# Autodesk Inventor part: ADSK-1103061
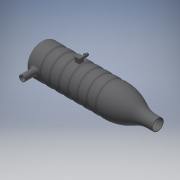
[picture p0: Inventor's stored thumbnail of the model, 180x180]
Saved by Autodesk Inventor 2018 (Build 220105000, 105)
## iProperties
Shininess: 50.0
Length Units: 11272
Angle Units: 11279
Time Units: 11290
Mass Units: 11286
Length Display Precision: 4
Angle Display Precision: 2
Compacted: True
Created: 2000-08
Part Number: ADSK-1103061
Document SubType Name: Modeling
Description: EXHAUST PIPE - SIDE
Mass: 7.18318 g
Surface Area: 233.725 cm^2
Volume: 7.18318 cm^3
Density: 1 g/cm^3
Material: Generic
Appearance: Black
Density: 0.0
Volumn: 0.0
Area: 0.0
PropertySet Name: Model Information
Control State: 0
Master: False
Checked Out: False
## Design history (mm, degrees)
node "Revolution1" dims "d8" = 90 deg
  sketch "Sketch3"
    geometry: L1 (33.387, 39.395)-(33.387, -87.605); L2 (49.262, -64.093)-(49.262, -4.86); L3 (39.387, 32.722)-(39.387, 39.395); L4 (39.387, 39.395)-(33.387, 39.395); L5 (33.387, -87.605)-(36.562, -87.605); L6 (36.562, -87.605)-(49.262, -79.35); L7 (49.262, -79.35)-(49.262, -64.093); L8 (42.607, 20.345)-(43.458, 18.72); A1 r 25.4 centre (64.787, 32.722) between (39.387, 32.722) and (42.607, 20.345); A2 r 50.8 centre (-1.538, -4.86) between (49.262, -4.86) and (43.458, 18.72); 1 further point
    constraints: 16 end point, 4 point on circle, 3 parallel, 3 tangent, 2 centre point, 2 perpendicular, 2 point on line, 1 vertical, 1 other
    dimensions: "d1" = 6.35 diameter of L5.end L1; "d2" = 31.75 diameter of L2.start L1; "d5" = 8.255 vertical distance of L5.end L6.end; "d6" = 127 distance of L1.start L1.end; "d7" = 12 diameter of L3 L1; "d48" = 25.4 radius of A1; "d49" = 6.67308 distance from line of L4 A1.centre; "d50" = 19.05 distance from line of L4 L8.start; "d51" = 31.75 distance from line of point (49.262, 7.645) L4; "d53" = 50.8 radius of A2
node "Fillet1" dims "d9" = 3.175
workaxis "Work Axis1"
node "Revolution2" dims "d15" = 90 deg
  sketch "Sketch4"
    geometry: L1 (49.262, -4.86)-(49.262, -77.627) reference; L2 (33.387, 64.795)-(33.387, -113.005) reference; L3 (49.262, -6.96)-(48.373, -7.595); L4 (48.373, -7.595)-(48.373, -8.865); L5 (48.373, -8.865)-(49.262, -9.5); L6 (27.387, 39.395)-(39.387, 39.395) reference
    constraints: 6 end point, 2 point on line, 1 equal length, 1 parallel
    dimensions: "d11" = 1.27 distance of L3.end L4.end; "d12" = 2.54 distance of L5.end L3.start; "d13" = 46.355 distance from line of L6 L3.start; "d14" = 14.986 distance between parallel lines of L2 L4
node "Fillet2" dims "d16" = 3.175
node "Rectangular Pattern1" dims "d17" = 70, "d19" = 9.525
workplane "Work Plane1"
workplane "Work Plane2"
node "Extrusion1" dims "d23" = 25.4, "d24" = 0
  sketch "Sketch5"
    geometry: L1 (136.516, 0)-(-41.284, 0) reference; L2 (111.116, 6)-(111.116, -6) reference; C1 r 3.175 at (-0.009, 0)
    constraints: 1 centre point, 1 point on line
    dimensions: "d22" = 6.35 diameter of C1; "d54" = 111.125 distance from line of L2 C1.centre
node "Shell1" dims "d25" = 0.6096
node "Fillet5" dims "d81" = 2.54
workaxis "Work Axis2"
workplane "Work Plane3"
workplane "Work Plane4"
node "Extrusion2" dims "d82" = 0, "d83" = 4.7625 (= d85)
  sketch "Sketch6"
    geometry: L1 (-6.25, 20.108)-(-1.487, 20.108); L2 (-1.487, 20.108)-(-1.487, 24.871); L3 (-1.487, 24.871)-(-6.25, 24.871); L4 (-6.25, 24.871)-(-6.25, 20.108); L5 (-3.869, 128.672)-(-3.869, -49.128) reference
    constraints: 8 end point, 2 parallel, 1 horizontal, 1 perpendicular
    dimensions: "d85" = 4.7625 distance of L1.end L2.end; "d84" = 4.7625 distance of L2.end L3.end (= d85); "d98" = 2.38125 distance between parallel lines of L2 L5 (= 0.5 x d84)
node "Extrusion3" dims "d86" = 0, "d87" = 3.175
  sketch "Sketch7"
    geometry: L1 (4.763, 0)-(4.763, 4.762) reference; L2 (0, 4.762)-(4.763, 4.762) reference; C1 r 1.27 at (2.381, 2.381)
    constraints: 1 centre point
    dimensions: "d88" = 2.54 diameter of C1; "d90" = 2.38125 distance from line of C1.centre L2 (= 0.5 x d85); "d89" = 2.38125 distance from line of L1 C1.centre (= d90)
node "Extrusion4" dims "d91" = -12 deg, "d92" = 3.175
  sketch "Sketch8"
    geometry: C1 r 1.27 at (0, 0) reference; C2 r 1.905 at (0, 0)
    constraints: 1 centre point, 1 coincident
    dimensions: "d93" = 3.81 diameter of C2
node "Extrusion6" dims "d104" = 25.4, "d105" = 0
  sketch "Sketch12"
    geometry: L1 (-6.25, 20.108)-(-6.25, 24.871) reference; L2 (-1.487, 20.108)-(-6.25, 20.108) reference; L3 (-1.487, 24.871)-(-1.487, 20.108) reference; L4 (-6.25, 24.871)-(-1.487, 24.871) reference
node "Extrusion5" dims "d94" = 0, "d95" = 10.795
  sketch "Sketch9"
    geometry: C1 r 1.23 at (0, 0) reference; C2 r 1.048 at (0, 0)
    constraints: 1 centre point, 1 coincident
    dimensions: "d96" = 2.0955 diameter of C2
body "Solid1"
other parameters: "d21" = -12.7
